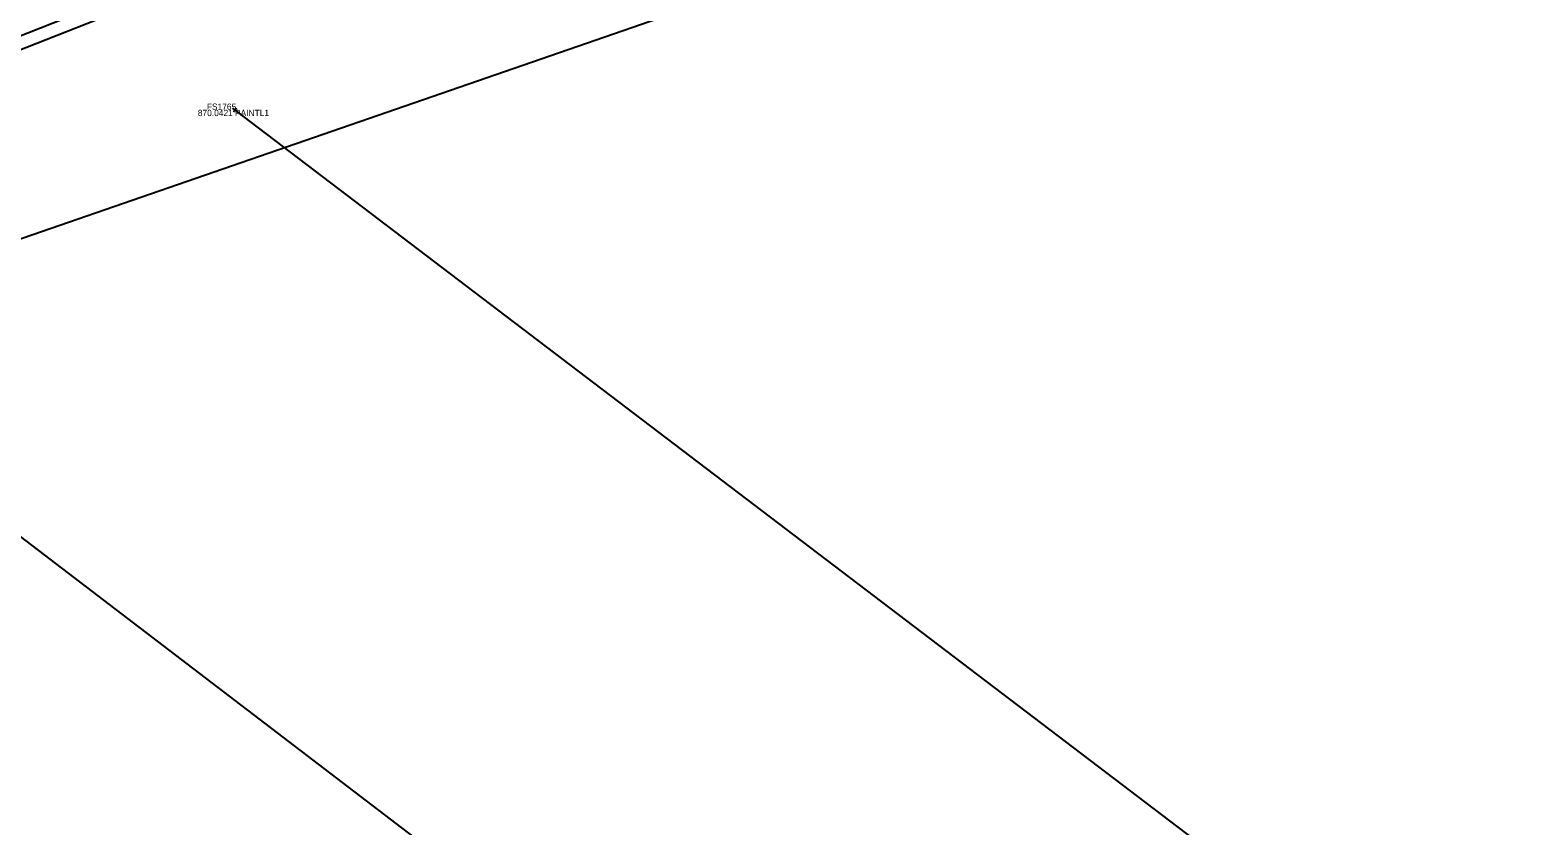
# Model space of a CAD drawing. Extents: x 1479425 to 1480294, y 379351 to 380102.
# Drawn here: x 1479669.9 to 1479684.31, y 379936.02 to 379943.62 of the extents above; entities that cross this region are included whole.
import ezdxf

# ---------------------------------------------------------------- set-up
doc = ezdxf.new("R2010")
doc.units = 0
for name, color, linetype in [('PM_X_Crosswalk', 7, 'Continuous'), ('PV_X_Curb', 7, 'Continuous'), ('SV_X_Shot_Marker', 7, 'Continuous'), ('SV_X_Text_Comment', 7, 'Continuous'), ('SV_X_Text_Elevation', 7, 'Continuous'), ('SV_X_Text_Name', 7, 'Continuous'), ('UT_X_Gas', 7, 'Continuous'), ('UT_X_Sanitary_Line', 7, 'Continuous')]:
    doc.layers.add(name, color=color, linetype=linetype)

msp = doc.modelspace()

# ---------------------------------------------------------------- linework, layer by layer
at = {"layer": 'PM_X_Crosswalk'}
msp.add_lwpolyline([(1479696.985, 379923.758), (1479671.854, 379942.855)], dxfattribs=at)
at = {"layer": 'PV_X_Curb'}
for points in [[(1479791.848, 380002.989), (1479773.254, 379993.873), (1479762.766, 379988.772), (1479738.122, 379976.643), (1479720.845, 379968.214), (1479698.694, 379957.239), (1479682.744, 379949.362), (1479678.802, 379947.48), (1479675.687, 379946.021), (1479671.323, 379944.026), (1479668.99, 379943.106), (1479665.638, 379942.041), (1479664.143, 379941.582), (1479662.026, 379941.397), (1479659.994, 379941.512), (1479654.023, 379942.767), (1479648.758, 379945.101), (1479643.81, 379948.553)], [(1479664.204, 379941.738), (1479664.738, 379941.853), (1479664.919, 379941.918), (1479667.085, 379942.594), (1479669.039, 379943.263), (1479671.07, 379944.064), (1479673.811, 379945.322), (1479675.836, 379946.224), (1479678.71, 379947.573), (1479678.867, 379947.609), (1479682.623, 379949.494)]]:
    msp.add_lwpolyline(points, dxfattribs=at)
at = {"layer": 'SV_X_Shot_Marker'}
for p, q in [((1479671.874, 379942.839), (1479671.834, 379942.87)), ((1479671.839, 379942.835), (1479671.869, 379942.874)), ((1479671.854, 379942.855), (1479671.854, 379942.855))]:
    msp.add_line(p, q, dxfattribs=at)
at = {"layer": 'UT_X_Gas'}
msp.add_lwpolyline([(1479667.444, 379946.572), (1479666.862, 379942.802), (1479667.538, 379940.507), (1479675.403, 379934.504), (1479682.743, 379926.326), (1479692.421, 379916.824), (1479702.659, 379906.694), (1479713.881, 379895.567), (1479724.225, 379885.781), (1479733.117, 379877.795), (1479742.697, 379869.326), (1479754.816, 379857.131), (1479762.869, 379849.318), (1479772.436, 379840.641), (1479780.346, 379832.715), (1479784.901, 379828.191), (1479795.906, 379818.324), (1479806.128, 379806.719), (1479816.671, 379794.927)], dxfattribs=at)
at = {"layer": 'UT_X_Sanitary_Line'}
msp.add_lwpolyline([(1479514.622, 379866.87), (1479542.109, 379880.195), (1479565.169, 379891.725), (1479588.442, 379902.577), (1479600.276, 379909.045), (1479620.421, 379921.063), (1479621.963, 379921.485), (1479624.647, 379923.417), (1479645.234, 379932.512), (1479652.585, 379935.616), (1479664.157, 379939.675), (1479679.103, 379944.837), (1479710.112, 379956.448), (1479736.037, 379968.233), (1479798.147, 379991.168), (1479820.4, 379999.933), (1479823.042, 380000.22)], dxfattribs=at)

# ---------------------------------------------------------------- texts
at = {"layer": 'SV_X_Text_Comment'}
msp.add_text('PAINTL1', height=0.06, dxfattribs=at).set_placement((1479671.854, 379942.795))
at = {"layer": 'SV_X_Text_Elevation'}
msp.add_text('870.0421', height=0.06, dxfattribs=at).set_placement((1479671.499, 379942.795))
at = {"layer": 'SV_X_Text_Name'}
msp.add_text('FS1765', height=0.06, dxfattribs=at).set_placement((1479671.585, 379942.855))

doc.saveas('drawing.dxf')
